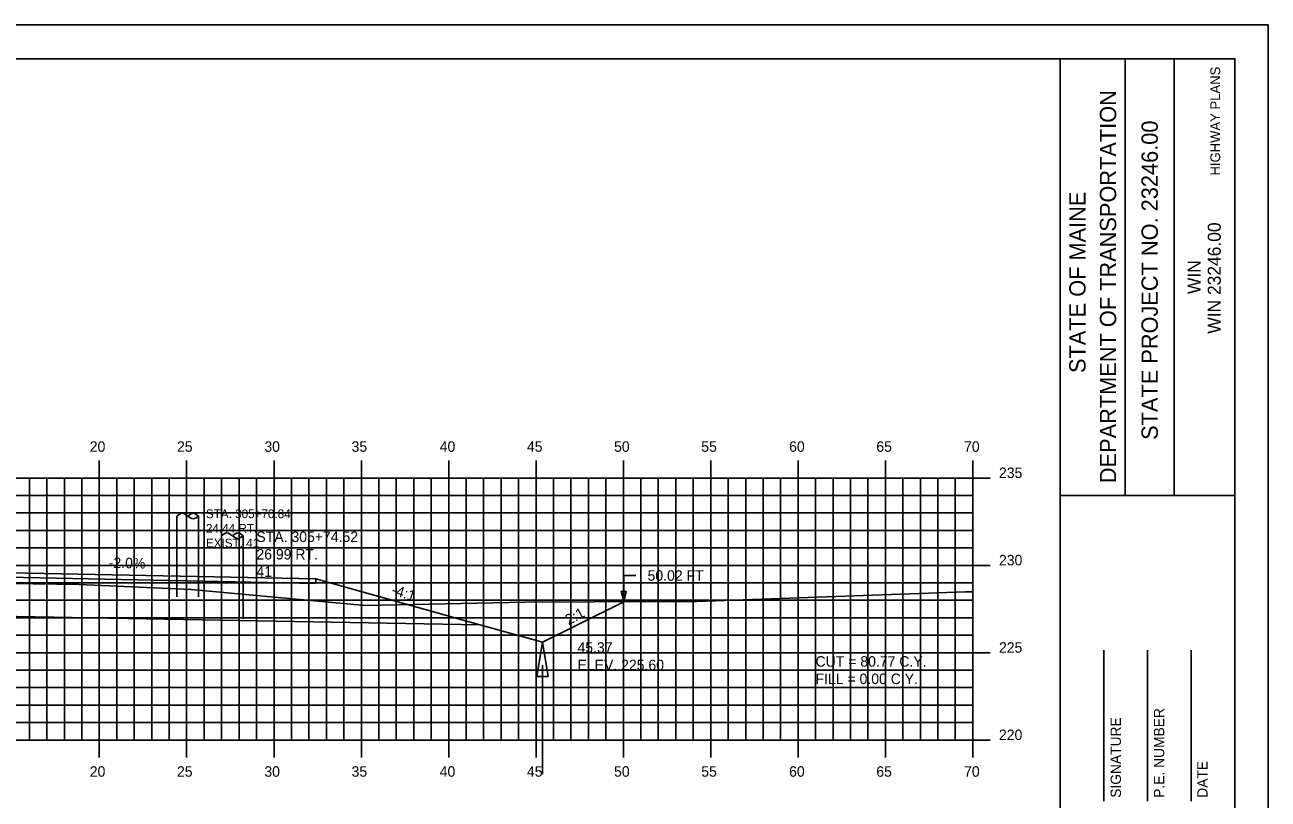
# Model space of a CAD drawing. Extents: x 1137211 to 1137381, y 608981 to 609091.
# Drawn here: x 1137309.6 to 1137380.8, y 609047 to 609091.3 of the extents above; entities that cross this region are included whole.
import ezdxf

# ---------------------------------------------------------------- set-up
doc = ezdxf.new("R2010")
doc.units = 0
for name, color, linetype in [('ANNOTATION', 7, 'Continuous'), ('BORDER', 7, 'Continuous'), ('D_Drainage_Ditch_Line', 7, 'Continuous'), ('D_Roadway_Edge_Shoulder', 7, 'Continuous'), ('D_Roadway_SlopeLines', 7, 'Continuous'), ('D_Roadway_SubGrade', 7, 'Continuous'), ('D_Text_Monospaced', 7, 'Continuous'), ('D_Text_Standard', 7, 'Continuous'), ('D_Utilities_Pole_Joint_Rt', 7, 'Continuous'), ('H_V ANNOTATION', 7, 'Continuous'), ('HIGHWAY_TITLE', 7, 'Continuous'), ('MAJOR', 7, 'Continuous'), ('MINOR', 7, 'Continuous'), ('PLOT BOUNDARY', 7, 'Continuous'), ('S_Roadway_Centerline', 7, 'Continuous'), ('S_Utilities_Pole_Power', 7, 'Continuous')]:
    doc.layers.add(name, color=color, linetype=linetype)

msp = doc.modelspace()

# ---------------------------------------------------------------- linework, layer by layer
at = {"layer": 'BORDER'}
for p, q in [((1137368.897, 608984.335), (1137368.897, 609089.335)), ((1137372.625, 609064.332), (1137372.625, 609089.332)), ((1137375.42, 609064.332), (1137375.42, 609089.332)), ((1137368.897, 609064.329), (1137378.897, 609064.329)), ((1137371.397, 609046.838), (1137371.397, 609055.485)), ((1137373.897, 609046.838), (1137373.897, 609055.485)), ((1137376.397, 609046.838), (1137376.397, 609055.485))]:
    msp.add_line(p, q, dxfattribs=at)
msp.add_lwpolyline([(1137218.897, 608984.335), (1137378.897, 608984.335), (1137378.897, 609089.335), (1137218.897, 609089.335)], close=True, dxfattribs=at)
at = {"layer": 'D_Drainage_Ditch_Line'}
msp.add_line((1137339.269, 609054.622), (1137339.269, 609048.378), dxfattribs=at)
msp.add_lwpolyline([(1137339.597, 609053.966), (1137338.941, 609053.966), (1137339.269, 609055.934)], close=True, dxfattribs=at)
at = {"layer": 'D_Roadway_Edge_Shoulder'}
msp.add_lwpolyline([(1137304.896, 609059.983), (1137326.284, 609059.555), (1137326.284, 609059.305), (1137304.896, 609059.733)], close=True, dxfattribs=at)
at = {"layer": 'D_Roadway_SlopeLines'}
for points in [[(1137339.269, 609055.934), (1137341.269, 609056.934), (1137343.913, 609058.256)], [(1137335.681, 609056.925), (1137339.269, 609055.934)]]:
    msp.add_lwpolyline(points, dxfattribs=at)
at = {"layer": 'D_Roadway_SubGrade'}
msp.add_lwpolyline([(1137304.896, 609059.566), (1137304.896, 609059.733), (1137326.284, 609059.305), (1137326.284, 609059.555), (1137326.284, 609059.555), (1137335.681, 609056.925), (1137304.896, 609057.483)], close=True, dxfattribs=at)
at = {"layer": 'D_Text_Standard'}
msp.add_lwpolyline([(1137343.913, 609058.256), (1137343.92, 609059.753), (1137344.6, 609059.753)], dxfattribs=at)
msp.add_lwpolyline([(1137343.913, 609058.256), (1137343.77, 609058.839), (1137344.061, 609058.838)], close=True, dxfattribs=at)
at = {"layer": 'D_Utilities_Pole_Joint_Rt'}
for p, q in [((1137320.888, 609062.032), (1137321.044, 609062.142)), ((1137320.888, 609057.274), (1137320.888, 609062.032)), ((1137321.356, 609062.142), (1137321.513, 609062.032)), ((1137321.669, 609062.142), (1137321.513, 609062.032)), ((1137321.513, 609062.032), (1137321.669, 609061.921)), ((1137322.138, 609062.032), (1137321.982, 609062.142)), ((1137321.982, 609061.921), (1137322.138, 609062.032)), ((1137322.138, 609057.274), (1137322.138, 609062.032))]:
    msp.add_line(p, q, dxfattribs=at)
for centre, start, end in [((1137321.2, 609061.921), 90, 125.26439), ((1137321.2, 609061.921), 54.73561, 90), ((1137321.825, 609061.921), 90, 125.26439), ((1137321.825, 609062.142), 234.73561, 270), ((1137321.825, 609061.921), 54.73561, 90), ((1137321.825, 609062.142), 270, 305.26439)]:
    msp.add_arc(centre, 0.271, start, end, dxfattribs=at)
at = {"layer": 'MAJOR'}
for p, q in [((1137313.896, 609066.337), (1137313.896, 609065.335)), ((1137318.896, 609066.337), (1137318.896, 609065.335)), ((1137323.896, 609066.337), (1137323.896, 609065.335)), ((1137328.896, 609066.337), (1137328.896, 609065.335)), ((1137333.896, 609066.337), (1137333.896, 609065.335)), ((1137338.896, 609066.337), (1137338.896, 609065.335)), ((1137343.896, 609066.337), (1137343.896, 609065.335)), ((1137348.896, 609066.337), (1137348.896, 609065.335)), ((1137353.896, 609066.337), (1137353.896, 609065.335)), ((1137358.896, 609066.337), (1137358.896, 609065.335)), ((1137363.896, 609066.337), (1137363.896, 609065.335)), ((1137223.896, 609065.335), (1137363.896, 609065.335)), ((1137223.896, 609065.335), (1137363.896, 609065.335)), ((1137313.896, 609050.335), (1137313.896, 609065.335)), ((1137318.896, 609050.335), (1137318.896, 609065.335)), ((1137323.896, 609050.335), (1137323.896, 609065.335)), ((1137328.896, 609050.335), (1137328.896, 609065.335)), ((1137333.896, 609050.335), (1137333.896, 609065.335)), ((1137338.896, 609050.335), (1137338.896, 609065.335)), ((1137343.896, 609050.335), (1137343.896, 609065.335)), ((1137348.896, 609050.335), (1137348.896, 609065.335)), ((1137353.896, 609050.335), (1137353.896, 609065.335)), ((1137358.896, 609050.335), (1137358.896, 609065.335)), ((1137364.898, 609065.335), (1137362.894, 609065.335)), ((1137363.896, 609050.335), (1137363.896, 609065.335)), ((1137363.896, 609050.335), (1137363.896, 609065.335)), ((1137223.896, 609060.335), (1137363.896, 609060.335)), ((1137364.898, 609060.335), (1137362.894, 609060.335)), ((1137223.896, 609055.335), (1137363.896, 609055.335)), ((1137364.898, 609055.335), (1137362.894, 609055.335)), ((1137223.896, 609050.335), (1137363.896, 609050.335)), ((1137223.896, 609050.335), (1137363.896, 609050.335)), ((1137313.896, 609049.333), (1137313.896, 609050.335)), ((1137318.896, 609049.333), (1137318.896, 609050.335)), ((1137323.896, 609049.333), (1137323.896, 609050.335)), ((1137328.896, 609049.333), (1137328.896, 609050.335)), ((1137333.896, 609049.333), (1137333.896, 609050.335)), ((1137338.896, 609049.333), (1137338.896, 609050.335)), ((1137343.896, 609049.333), (1137343.896, 609050.335)), ((1137348.896, 609049.333), (1137348.896, 609050.335)), ((1137353.896, 609049.333), (1137353.896, 609050.335)), ((1137358.896, 609049.333), (1137358.896, 609050.335)), ((1137364.898, 609050.335), (1137362.894, 609050.335)), ((1137363.896, 609049.333), (1137363.896, 609050.335))]:
    msp.add_line(p, q, dxfattribs=at)
at = {"layer": 'MINOR'}
for p, q in [((1137309.896, 609050.335), (1137309.896, 609065.335)), ((1137310.896, 609050.335), (1137310.896, 609065.335)), ((1137311.896, 609050.335), (1137311.896, 609065.335)), ((1137312.896, 609050.335), (1137312.896, 609065.335)), ((1137314.896, 609050.335), (1137314.896, 609065.335)), ((1137315.896, 609050.335), (1137315.896, 609065.335)), ((1137316.896, 609050.335), (1137316.896, 609065.335)), ((1137317.896, 609050.335), (1137317.896, 609065.335)), ((1137319.896, 609050.335), (1137319.896, 609065.335)), ((1137320.896, 609050.335), (1137320.896, 609065.335)), ((1137321.896, 609050.335), (1137321.896, 609065.335)), ((1137322.896, 609050.335), (1137322.896, 609065.335)), ((1137324.896, 609050.335), (1137324.896, 609065.335)), ((1137325.896, 609050.335), (1137325.896, 609065.335)), ((1137326.896, 609050.335), (1137326.896, 609065.335)), ((1137327.896, 609050.335), (1137327.896, 609065.335)), ((1137329.896, 609050.335), (1137329.896, 609065.335)), ((1137330.896, 609050.335), (1137330.896, 609065.335)), ((1137331.896, 609050.335), (1137331.896, 609065.335)), ((1137332.896, 609050.335), (1137332.896, 609065.335)), ((1137334.896, 609050.335), (1137334.896, 609065.335)), ((1137335.896, 609050.335), (1137335.896, 609065.335)), ((1137336.896, 609050.335), (1137336.896, 609065.335)), ((1137337.896, 609050.335), (1137337.896, 609065.335)), ((1137339.896, 609050.335), (1137339.896, 609065.335)), ((1137340.896, 609050.335), (1137340.896, 609065.335)), ((1137341.896, 609050.335), (1137341.896, 609065.335)), ((1137342.896, 609050.335), (1137342.896, 609065.335)), ((1137344.896, 609050.335), (1137344.896, 609065.335)), ((1137345.896, 609050.335), (1137345.896, 609065.335)), ((1137346.896, 609050.335), (1137346.896, 609065.335)), ((1137347.896, 609050.335), (1137347.896, 609065.335)), ((1137349.896, 609050.335), (1137349.896, 609065.335)), ((1137350.896, 609050.335), (1137350.896, 609065.335)), ((1137351.896, 609050.335), (1137351.896, 609065.335)), ((1137352.896, 609050.335), (1137352.896, 609065.335)), ((1137354.896, 609050.335), (1137354.896, 609065.335)), ((1137355.896, 609050.335), (1137355.896, 609065.335)), ((1137356.896, 609050.335), (1137356.896, 609065.335)), ((1137357.896, 609050.335), (1137357.896, 609065.335)), ((1137359.896, 609050.335), (1137359.896, 609065.335)), ((1137360.896, 609050.335), (1137360.896, 609065.335)), ((1137361.896, 609050.335), (1137361.896, 609065.335)), ((1137362.896, 609050.335), (1137362.896, 609065.335)), ((1137223.896, 609064.335), (1137363.896, 609064.335)), ((1137363.896, 609064.335), (1137362.894, 609064.335)), ((1137223.896, 609063.335), (1137363.896, 609063.335)), ((1137363.896, 609063.335), (1137362.894, 609063.335)), ((1137223.896, 609062.335), (1137363.896, 609062.335)), ((1137363.896, 609062.335), (1137362.894, 609062.335)), ((1137223.896, 609061.335), (1137363.896, 609061.335)), ((1137363.896, 609061.335), (1137362.894, 609061.335)), ((1137223.896, 609059.335), (1137363.896, 609059.335)), ((1137363.896, 609059.335), (1137362.894, 609059.335)), ((1137223.896, 609058.335), (1137363.896, 609058.335)), ((1137363.896, 609058.335), (1137362.894, 609058.335)), ((1137223.896, 609057.335), (1137363.896, 609057.335)), ((1137363.896, 609057.335), (1137362.894, 609057.335)), ((1137223.896, 609056.335), (1137363.896, 609056.335)), ((1137363.896, 609056.335), (1137362.894, 609056.335)), ((1137223.896, 609054.335), (1137363.896, 609054.335)), ((1137363.896, 609054.335), (1137362.894, 609054.335)), ((1137223.896, 609053.335), (1137363.896, 609053.335)), ((1137363.896, 609053.335), (1137362.894, 609053.335)), ((1137223.896, 609052.335), (1137363.896, 609052.335)), ((1137363.896, 609052.335), (1137362.894, 609052.335)), ((1137223.896, 609051.335), (1137363.896, 609051.335)), ((1137363.896, 609051.335), (1137362.894, 609051.335))]:
    msp.add_line(p, q, dxfattribs=at)
at = {"layer": 'PLOT BOUNDARY'}
msp.add_lwpolyline([(1137210.803, 608981.276), (1137380.803, 608981.276), (1137380.803, 609091.276), (1137210.803, 609091.276)], close=True, dxfattribs=at)
at = {"layer": 'S_Roadway_Centerline'}
msp.add_lwpolyline([(1137308.838, 609059.302), (1137312.741, 609059.235), (1137319.156, 609058.959), (1137329.106, 609058.045), (1137338.262, 609058.23), (1137346.197, 609058.267), (1137348.099, 609058.268), (1137363.471, 609058.816), (1137363.896, 609058.827)], dxfattribs=at)
at = {"layer": 'S_Utilities_Pole_Power'}
for p, q in [((1137318.333, 609058.539), (1137318.33, 609063.159)), ((1137318.333, 609063.159), (1137318.489, 609063.269)), ((1137318.801, 609063.269), (1137318.958, 609063.159)), ((1137319.114, 609063.269), (1137318.958, 609063.159)), ((1137318.958, 609063.159), (1137319.114, 609063.048)), ((1137319.583, 609063.159), (1137319.427, 609063.269)), ((1137319.427, 609063.048), (1137319.583, 609063.159)), ((1137319.583, 609058.539), (1137319.58, 609063.159))]:
    msp.add_line(p, q, dxfattribs=at)
for centre, start, end in [((1137318.645, 609063.048), 90, 125.26439), ((1137318.645, 609063.048), 54.73561, 90), ((1137319.27, 609063.048), 90, 125.26439), ((1137319.27, 609063.269), 234.73561, 270), ((1137319.27, 609063.048), 54.73561, 90), ((1137319.27, 609063.269), 270, 305.26439)]:
    msp.add_arc(centre, 0.271, start, end, dxfattribs=at)

# ---------------------------------------------------------------- texts
at = {"layer": 'ANNOTATION'}
for s, rotation, p in [('-2.0%', 358.85424, (1137314.433, 609060.192)), ('-4:1', 342.08094, (1137330.572, 609058.691)), ('2:1', 28.32425, (1137340.762, 609056.898))]:
    msp.add_text(s, height=0.6, rotation=rotation, dxfattribs=at).set_placement(p)
at = {"layer": 'BORDER'}
for s, height, p in [('DEPARTMENT OF TRANSPORTATION', 0.93176, (1137372.103, 609065.041)), ('STATE PROJECT NO. 23246.00', 0.93176, (1137374.488, 609067.517)), ('STATE OF MAINE', 0.93176, (1137370.352, 609071.347)), ('WIN 23246.00', 0.74527, (1137378.092, 609073.596)), ('WIN', 0.7453, (1137376.933, 609075.865)), ('P.E. NUMBER', 0.59055, (1137374.857, 609047.03)), ('SIGNATURE', 0.5906, (1137372.377, 609047.03)), ('DATE', 0.5906, (1137377.338, 609047.03))]:
    msp.add_text(s, height=height, rotation=90, dxfattribs=at).set_placement(p)
at = {"layer": 'D_Text_Monospaced'}
for s, height, p in [('STA. 305+70.84', 0.49998, (1137320, 609063.037)), ('24.44 RT.', 0.5, (1137320, 609062.203)), ('EXIST. 41', 0.5, (1137320, 609061.363))]:
    msp.add_text(s, height=height, dxfattribs=at).set_placement(p)
at = {"layer": 'D_Text_Standard'}
for s, p in [('STA. 305+74.52', (1137322.888, 609061.672)), ('26.99 RT.', (1137322.888, 609060.67)), ('41 ', (1137322.888, 609059.674)), ('50.02 FT', (1137345.28, 609059.453)), ('45.37', (1137341.269, 609055.334)), ('ELEV. 225.60', (1137341.269, 609054.332)), ('CUT = 80.77 C.Y.', (1137354.896, 609054.535)), ('FILL = 0.00 C.Y.', (1137354.896, 609053.539))]:
    msp.add_text(s, height=0.6, dxfattribs=at).set_placement(p)
at = {"layer": 'H_V ANNOTATION'}
for s, p in [('20', (1137313.35, 609066.835)), ('25', (1137318.342, 609066.835)), ('30', (1137323.345, 609066.835)), ('35', (1137328.337, 609066.835)), ('40', (1137333.382, 609066.835)), ('45', (1137338.374, 609066.835)), ('50', (1137343.361, 609066.835)), ('55', (1137348.353, 609066.835)), ('60', (1137353.382, 609066.835)), ('65', (1137358.374, 609066.835)), ('70', (1137363.398, 609066.835)), ('235', (1137365.396, 609065.335)), ('230', (1137365.396, 609060.335)), ('225', (1137365.396, 609055.335)), ('220', (1137365.396, 609050.335)), ('20', (1137313.35, 609048.235)), ('25', (1137318.342, 609048.235)), ('30', (1137323.345, 609048.235)), ('35', (1137328.337, 609048.235)), ('40', (1137333.382, 609048.235)), ('45', (1137338.374, 609048.235)), ('50', (1137343.361, 609048.235)), ('55', (1137348.353, 609048.235)), ('60', (1137353.382, 609048.235)), ('65', (1137358.374, 609048.235)), ('70', (1137363.398, 609048.235))]:
    msp.add_text(s, height=0.6, dxfattribs=at).set_placement(p)
at = {"layer": 'HIGHWAY_TITLE'}
msp.add_text('HIGHWAY PLANS', height=0.55901, rotation=90, dxfattribs=at).set_placement((1137378.055, 609082.65))

doc.saveas('drawing.dxf')
